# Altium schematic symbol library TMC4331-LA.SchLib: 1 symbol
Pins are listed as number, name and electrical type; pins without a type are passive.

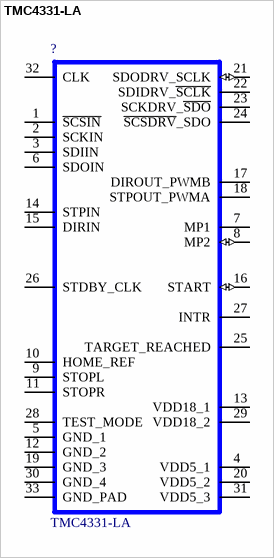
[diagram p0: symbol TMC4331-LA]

## TMC4331-LA
designator ?
Motion Controller, no ENC;  QFN32(4x4); Manufacturer: TRINAMIC; Geometry.Height: 0.9mm
footprint TMC_QFN32_0.4_4.0X4.0
pins: 1 ~{SCSIN}, 2 SCKIN, 3 SDIIN, 4 VDD5_1 (power), 5 GND_1, 6 SDOIN, 7 MP1, 8 MP2 (io), 9 STOPL, 10 HOME_REF, 11 STOPR, 12 GND_2, 13 VDD18_1 (power), 14 STPIN, 15 DIRIN, 16 START (io), 17 DIROUT_PWMB, 18 STPOUT_PWMA, 19 GND_3, 20 VDD5_2 (power), 21 SDODRV_SCLK (io), 22 SDIDRV_~{SCLK}, 23 SCKDRV_~{SDO}, 24 ~{SCSDRV}_SDO, 25 TARGET_REACHED, 26 STDBY_CLK, 27 INTR, 28 TEST_MODE, 29 VDD18_2 (power), 30 GND_4, 31 VDD5_3 (power), 32 CLK, 33 GND_PAD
